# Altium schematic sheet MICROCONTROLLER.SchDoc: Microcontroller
size A3; CompanyName: ARDUINO; Organization: ARDUINO; SheetNumber: 11; SheetTotal: 51; RevAuthor: Silvio Navaretti
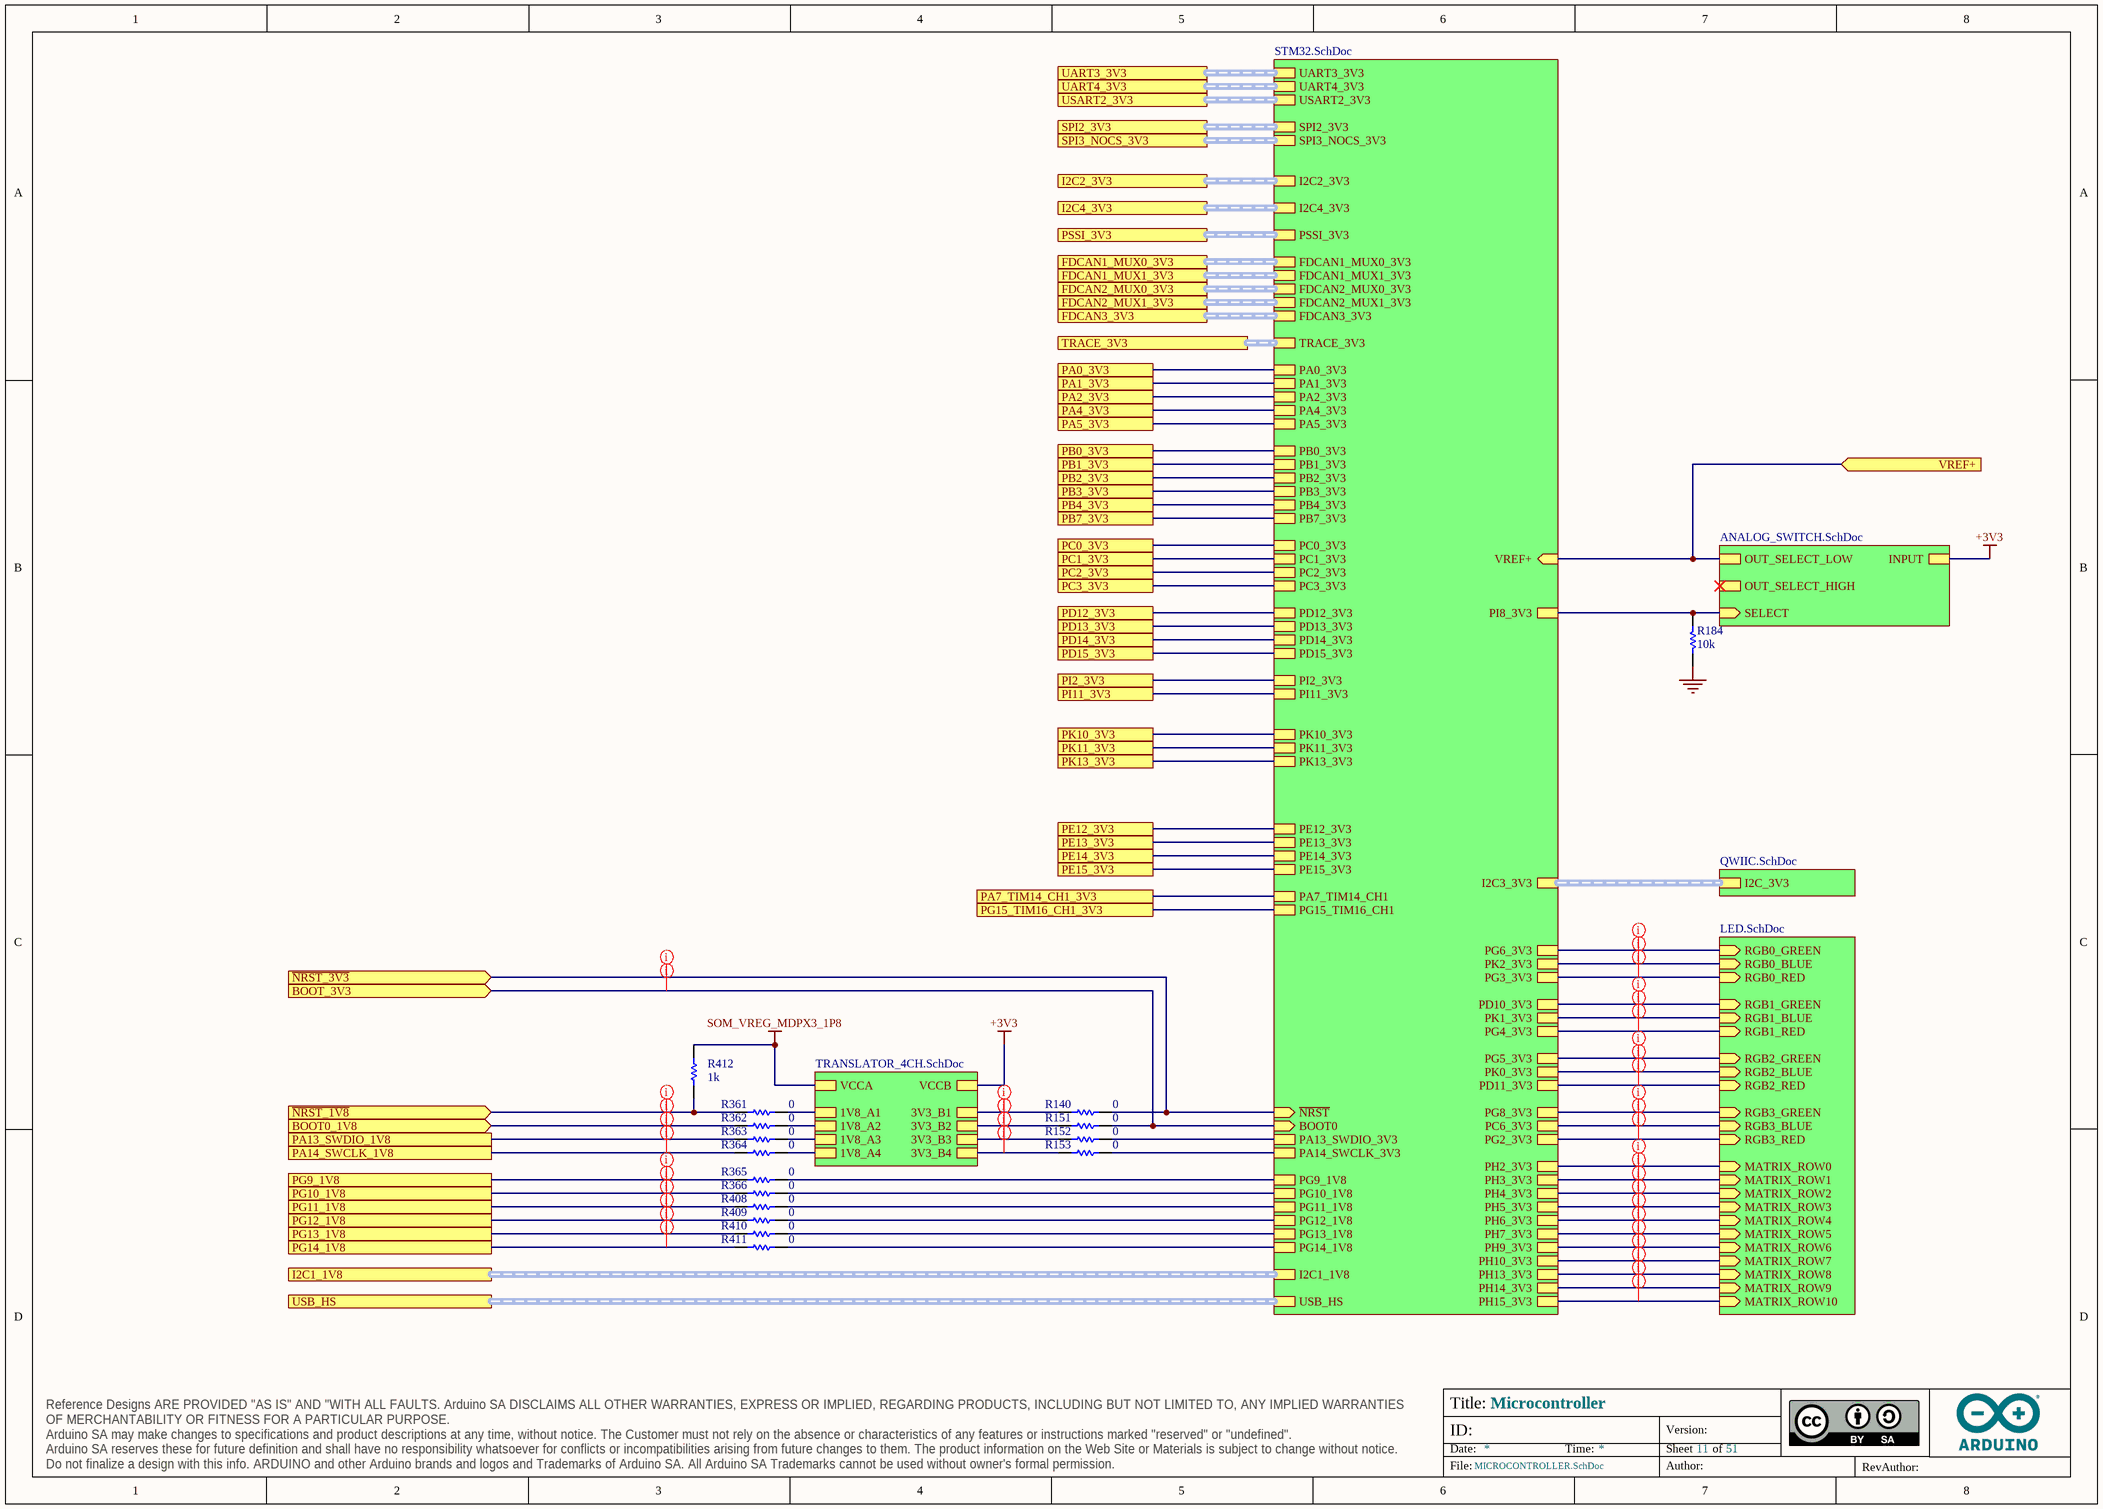
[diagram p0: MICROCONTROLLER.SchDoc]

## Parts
R140  value 0  [RES-0201]  (hidden comment: CRCW02010000Z0ED)
R151  value 0  [RES-0201]  (hidden comment: CRCW02010000Z0ED)
R152  value 0  [RES-0201]  (hidden comment: CRCW02010000Z0ED)
R153  value 0  [RES-0201]  (hidden comment: CRCW02010000Z0ED)
R184  value 10k  [RES-0201]  (hidden comment: RC0201FR-0710KL)
R361  value 0  [RES-0201]  (hidden comment: CRCW02010000Z0ED)
R362  value 0  [RES-0201]  (hidden comment: CRCW02010000Z0ED)
R363  value 0  [RES-0201]  (hidden comment: CRCW02010000Z0ED)
R364  value 0  [RES-0201]  (hidden comment: CRCW02010000Z0ED)
R365  value 0  [RES-0201]  (hidden comment: CRCW02010000Z0ED)
R366  value 0  [RES-0201]  (hidden comment: CRCW02010000Z0ED)
R408  value 0  [RES-0201]  (hidden comment: CRCW02010000Z0ED)
R409  value 0  [RES-0201]  (hidden comment: CRCW02010000Z0ED)
R410  value 0  [RES-0201]  (hidden comment: CRCW02010000Z0ED)
R411  value 0  [RES-0201]  (hidden comment: CRCW02010000Z0ED)
R412  value 1k  [RES-0201]  (hidden comment: RC0201FR-071KL)

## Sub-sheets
U_ANALOG_SWITCH = ANALOG_SWITCH.SchDoc: SELECT (in), OUT_SELECT_LOW, OUT_SELECT_HIGH, INPUT
U_LED = LED.SchDoc: RGB0_GREEN (in), RGB0_BLUE (in), RGB0_RED (in), RGB1_GREEN (in), RGB1_BLUE (in), RGB1_RED (in), RGB2_GREEN (in), RGB2_BLUE (in), RGB2_RED (in), RGB3_GREEN (in), RGB3_BLUE (in), RGB3_RED (in), MATRIX_ROW0 (in), MATRIX_ROW1 (in), MATRIX_ROW2 (in), MATRIX_ROW3 (in), MATRIX_ROW4 (in), MATRIX_ROW5 (in), MATRIX_ROW6 (in), MATRIX_ROW7 (in), MATRIX_ROW8 (in), MATRIX_ROW9 (in), MATRIX_ROW10 (in)
U_QWIIC = QWIIC.SchDoc: I2C_3V3 (harness I2C)
U_STM32 = STM32.SchDoc: USB_HS (harness SOM_MD_USB1), ~{NRST} (in), BOOT0 (in), UART3_3V3 (harness UART), PB2_3V3, PB3_3V3, FDCAN2_MUX0_3V3 (harness CAN), PB0_3V3, PB1_3V3, PB4_3V3, PB7_3V3, SPI2_3V3 (harness SPI), PA0_3V3, PA1_3V3, I2C2_3V3 (harness I2C), PA2_3V3, UART4_3V3 (harness UART), PSSI_3V3 (harness PSSI), PA4_3V3, PA5_3V3, PE12_3V3, PE13_3V3, PE14_3V3, PE15_3V3, FDCAN1_MUX0_3V3 (harness CAN), FDCAN2_MUX1_3V3 (harness CAN), PC0_3V3, PC1_3V3, PC2_3V3, PC3_3V3, PH2_3V3, PH3_3V3, PH4_3V3, PH5_3V3, PH6_3V3, PH7_3V3, PH9_3V3, PH13_3V3, PH14_3V3, PH15_3V3, VREF+ (in), SPI3_NOCS_3V3 (harness JSPI_SPI), I2C4_3V3 (harness I2C), PG9_1V8, PG10_1V8, PG11_1V8, PG12_1V8, PG13_1V8, PG14_1V8, I2C3_3V3 (harness I2C), I2C1_1V8 (harness I2C), PA13_SWDIO_3V3, PA14_SWCLK_3V3, TRACE_3V3 (harness MCU_TRACE), USART2_3V3 (harness UART), PA7_TIM14_CH1, PG15_TIM16_CH1, FDCAN3_3V3 (harness CAN), FDCAN1_MUX1_3V3 (harness CAN), PD12_3V3, PD13_3V3, PD14_3V3, PD15_3V3, PI2_3V3, PI11_3V3, PI8_3V3, PG2_3V3, PK0_3V3, PK1_3V3, PK2_3V3, PD10_3V3, PD11_3V3, PG3_3V3, PG4_3V3, PG5_3V3, PG6_3V3, PC6_3V3, PG8_3V3, PH10_3V3, PK13_3V3, PK10_3V3, PK11_3V3
U_TRANSLATOR_4CH = TRANSLATOR_4CH.SchDoc: 1V8_A1, 1V8_A2, 1V8_A3, 1V8_A4, 3V3_B1, 3V3_B2, 3V3_B3, 3V3_B4, VCCA, VCCB

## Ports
BOOT0_1V8 (in), BOOT_3V3 (in), FDCAN1_MUX0_3V3, FDCAN1_MUX1_3V3, FDCAN2_MUX0_3V3, FDCAN2_MUX1_3V3, FDCAN3_3V3, I2C1_1V8, I2C2_3V3, I2C4_3V3, PA0_3V3, PA1_3V3, PA2_3V3, PA4_3V3, PA5_3V3, PA7_TIM14_CH1_3V3, PA13_SWDIO_1V8, PA14_SWCLK_1V8, PB0_3V3, PB1_3V3, PB2_3V3, PB3_3V3, PB4_3V3, PB7_3V3, PC0_3V3, PC1_3V3, PC2_3V3, PC3_3V3, PD12_3V3, PD13_3V3, PD14_3V3, PD15_3V3, PE12_3V3, PE13_3V3, PE14_3V3, PE15_3V3, PG9_1V8, PG10_1V8, PG11_1V8, PG12_1V8, PG13_1V8, PG14_1V8, PG15_TIM16_CH1_3V3, PI2_3V3, PI11_3V3, PK10_3V3, PK11_3V3, PK13_3V3, PSSI_3V3, SPI2_3V3, SPI3_NOCS_3V3, TRACE_3V3, UART3_3V3, UART4_3V3, USART2_3V3, USB_HS, VREF+ (in), ~{NRST_1V8} (in), ~{NRST_3V3} (in)

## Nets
+3V3: sheet U_ANALOG_SWITCH/INPUT, sheet U_TRANSLATOR_4CH/VCCB
GND: R184.1
SOM_VREG_MDPX3_1P8: R412.1 ; sheet U_TRANSLATOR_4CH/VCCA
BOOT0_1V8: R362.2 ; port BOOT0_1V8
BOOT_3V3: R151.1 ; port BOOT_3V3, sheet U_STM32/BOOT0
~{NRST_1V8}: R361.2 R412.2 ; port ~{NRST_1V8}
~{NRST_3V3}: R140.1 ; port ~{NRST_3V3}, sheet U_STM32/~{NRST}
PA0_3V3: port PA0_3V3, sheet U_STM32/PA0_3V3
PA1_3V3: port PA1_3V3, sheet U_STM32/PA1_3V3
PA2_3V3: port PA2_3V3, sheet U_STM32/PA2_3V3
PA4_3V3: port PA4_3V3, sheet U_STM32/PA4_3V3
PA5_3V3: port PA5_3V3, sheet U_STM32/PA5_3V3
PA7_TIM14_CH1_3V3: port PA7_TIM14_CH1_3V3, sheet U_STM32/PA7_TIM14_CH1
PA13_SWDIO_1V8: R363.2 ; port PA13_SWDIO_1V8
PA14_SWCLK_1V8: R364.2 ; port PA14_SWCLK_1V8
PB0_3V3: port PB0_3V3, sheet U_STM32/PB0_3V3
PB1_3V3: port PB1_3V3, sheet U_STM32/PB1_3V3
PB2_3V3: port PB2_3V3, sheet U_STM32/PB2_3V3
PB3_3V3: port PB3_3V3, sheet U_STM32/PB3_3V3
PB4_3V3: port PB4_3V3, sheet U_STM32/PB4_3V3
PB7_3V3: port PB7_3V3, sheet U_STM32/PB7_3V3
PC0_3V3: port PC0_3V3, sheet U_STM32/PC0_3V3
PC1_3V3: port PC1_3V3, sheet U_STM32/PC1_3V3
PC2_3V3: port PC2_3V3, sheet U_STM32/PC2_3V3
PC3_3V3: port PC3_3V3, sheet U_STM32/PC3_3V3
PD12_3V3: port PD12_3V3, sheet U_STM32/PD12_3V3
PD13_3V3: port PD13_3V3, sheet U_STM32/PD13_3V3
PD14_3V3: port PD14_3V3, sheet U_STM32/PD14_3V3
PD15_3V3: port PD15_3V3, sheet U_STM32/PD15_3V3
PE12_3V3: port PE12_3V3, sheet U_STM32/PE12_3V3
PE13_3V3: port PE13_3V3, sheet U_STM32/PE13_3V3
PE14_3V3: port PE14_3V3, sheet U_STM32/PE14_3V3
PE15_3V3: port PE15_3V3, sheet U_STM32/PE15_3V3
PG9_1V8: R365.2 ; port PG9_1V8
PG10_1V8: R366.2 ; port PG10_1V8
PG11_1V8: R408.2 ; port PG11_1V8
PG12_1V8: R409.2 ; port PG12_1V8
PG13_1V8: R410.2 ; port PG13_1V8
PG14_1V8: R411.2 ; port PG14_1V8
PG15_TIM16_CH1_3V3: port PG15_TIM16_CH1_3V3, sheet U_STM32/PG15_TIM16_CH1
PI2_3V3: port PI2_3V3, sheet U_STM32/PI2_3V3
PI11_3V3: port PI11_3V3, sheet U_STM32/PI11_3V3
PK10_3V3: port PK10_3V3, sheet U_STM32/PK10_3V3
PK11_3V3: port PK11_3V3, sheet U_STM32/PK11_3V3
PK13_3V3: port PK13_3V3, sheet U_STM32/PK13_3V3
VREF+: port VREF+, sheet U_STM32/VREF+, sheet U_ANALOG_SWITCH/OUT_SELECT_LOW
NetR140_2: R140.2 ; sheet U_TRANSLATOR_4CH/3V3_B1
NetR151_2: R151.2 ; sheet U_TRANSLATOR_4CH/3V3_B2
NetR152_1: R152.1 ; sheet U_STM32/PA13_SWDIO_3V3
NetR152_2: R152.2 ; sheet U_TRANSLATOR_4CH/3V3_B3
NetR153_1: R153.1 ; sheet U_STM32/PA14_SWCLK_3V3
NetR153_2: R153.2 ; sheet U_TRANSLATOR_4CH/3V3_B4
NetR184_2: R184.2 ; sheet U_STM32/PI8_3V3, sheet U_ANALOG_SWITCH/SELECT
NetR361_1: R361.1 ; sheet U_TRANSLATOR_4CH/1V8_A1
NetR362_1: R362.1 ; sheet U_TRANSLATOR_4CH/1V8_A2
NetR363_1: R363.1 ; sheet U_TRANSLATOR_4CH/1V8_A3
NetR364_1: R364.1 ; sheet U_TRANSLATOR_4CH/1V8_A4
NetR365_1: R365.1 ; sheet U_STM32/PG9_1V8
NetR366_1: R366.1 ; sheet U_STM32/PG10_1V8
NetR408_1: R408.1 ; sheet U_STM32/PG11_1V8
NetR409_1: R409.1 ; sheet U_STM32/PG12_1V8
NetR410_1: R410.1 ; sheet U_STM32/PG13_1V8
NetR411_1: R411.1 ; sheet U_STM32/PG14_1V8
(unnamed): sheet U_STM32/PH2_3V3, sheet U_LED/MATRIX_ROW0
(unnamed): sheet U_STM32/PH3_3V3, sheet U_LED/MATRIX_ROW1  [a separate net that carries the same name]
(unnamed): sheet U_STM32/PH4_3V3, sheet U_LED/MATRIX_ROW2  [a separate net that carries the same name]
(unnamed): sheet U_STM32/PH5_3V3, sheet U_LED/MATRIX_ROW3  [a separate net that carries the same name]
(unnamed): sheet U_STM32/PH6_3V3, sheet U_LED/MATRIX_ROW4  [a separate net that carries the same name]
(unnamed): sheet U_STM32/PH7_3V3, sheet U_LED/MATRIX_ROW5  [a separate net that carries the same name]
(unnamed): sheet U_STM32/PH9_3V3, sheet U_LED/MATRIX_ROW6  [a separate net that carries the same name]
(unnamed): sheet U_STM32/PH13_3V3, sheet U_LED/MATRIX_ROW8  [a separate net that carries the same name]
(unnamed): sheet U_STM32/PH14_3V3, sheet U_LED/MATRIX_ROW9  [a separate net that carries the same name]
(unnamed): sheet U_STM32/PH15_3V3, sheet U_LED/MATRIX_ROW10  [a separate net that carries the same name]
(unnamed): sheet U_STM32/PG2_3V3, sheet U_LED/RGB3_RED  [a separate net that carries the same name]
(unnamed): sheet U_STM32/PK0_3V3, sheet U_LED/RGB2_BLUE  [a separate net that carries the same name]
(unnamed): sheet U_STM32/PK1_3V3, sheet U_LED/RGB1_BLUE  [a separate net that carries the same name]
(unnamed): sheet U_STM32/PK2_3V3, sheet U_LED/RGB0_BLUE  [a separate net that carries the same name]
(unnamed): sheet U_STM32/PD10_3V3, sheet U_LED/RGB1_GREEN  [a separate net that carries the same name]
(unnamed): sheet U_STM32/PD11_3V3, sheet U_LED/RGB2_RED  [a separate net that carries the same name]
(unnamed): sheet U_STM32/PG3_3V3, sheet U_LED/RGB0_RED  [a separate net that carries the same name]
(unnamed): sheet U_STM32/PG4_3V3, sheet U_LED/RGB1_RED  [a separate net that carries the same name]
(unnamed): sheet U_STM32/PG5_3V3, sheet U_LED/RGB2_GREEN  [a separate net that carries the same name]
(unnamed): sheet U_STM32/PG6_3V3, sheet U_LED/RGB0_GREEN  [a separate net that carries the same name]
(unnamed): sheet U_STM32/PC6_3V3, sheet U_LED/RGB3_BLUE  [a separate net that carries the same name]
(unnamed): sheet U_STM32/PG8_3V3, sheet U_LED/RGB3_GREEN  [a separate net that carries the same name]
(unnamed): sheet U_STM32/PH10_3V3, sheet U_LED/MATRIX_ROW7  [a separate net that carries the same name]

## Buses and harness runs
harness port FDCAN1_MUX0_3V3 = sheet U_STM32/FDCAN1_MUX0_3V3
harness port FDCAN1_MUX1_3V3 = sheet U_STM32/FDCAN1_MUX1_3V3
harness port FDCAN2_MUX0_3V3 = sheet U_STM32/FDCAN2_MUX0_3V3
harness port FDCAN2_MUX1_3V3 = sheet U_STM32/FDCAN2_MUX1_3V3
harness port FDCAN3_3V3 = sheet U_STM32/FDCAN3_3V3
harness port I2C1_1V8 = sheet U_STM32/I2C1_1V8
harness port I2C2_3V3 = sheet U_STM32/I2C2_3V3
harness port I2C4_3V3 = sheet U_STM32/I2C4_3V3
harness port PSSI_3V3 = sheet U_STM32/PSSI_3V3
harness port SPI2_3V3 = sheet U_STM32/SPI2_3V3
harness port SPI3_NOCS_3V3 = sheet U_STM32/SPI3_NOCS_3V3
harness port TRACE_3V3 = sheet U_STM32/TRACE_3V3
harness port UART3_3V3 = sheet U_STM32/UART3_3V3
harness port UART4_3V3 = sheet U_STM32/UART4_3V3
harness port USART2_3V3 = sheet U_STM32/USART2_3V3
harness port USB_HS = sheet U_STM32/USB_HS
harness sheet U_QWIIC/I2C_3V3 = sheet U_STM32/I2C3_3V3

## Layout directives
net class MICROCONTROLLER: BOOT0_1V8, BOOT_3V3, NetR140_2, NetR151_2, NetR152_2, NetR153_2, PA13_SWDIO_1V8, PA14_SWCLK_1V8, PG9_1V8, PG10_1V8, PG11_1V8, PG12_1V8, PG13_1V8, PG14_1V8, ~{NRST_1V8}, ~{NRST_3V3}
net class MICROCONTROLLER_RGB: (no net found under the mark)
net class MICROCONTROLLER_MATRIX: (no net found under the mark)

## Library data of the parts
R140 R151-R153 R361-R366 R408-R411 = R0140-A.21: RES CHIP 0201 0R; Manufacturer: Vishay; Temperature coefficient: 0ppm; Code Arduino: R0140; Power: 50mW; Tolerance: 0%
R184 = R0145-A.21: RES CHIP 0201 10k 1% 1/20W; Manufacturer: Yageo; Power: 50mW; Temperature coefficient: 200ppm; Code Arduino: R0145
R412 = R0195-A.22: RES CHIP 0201 1k 1% 1/20W; Manufacturer: Yageo; Power: 50mW; Temperature coefficient: 200ppm; Code Arduino: R0195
